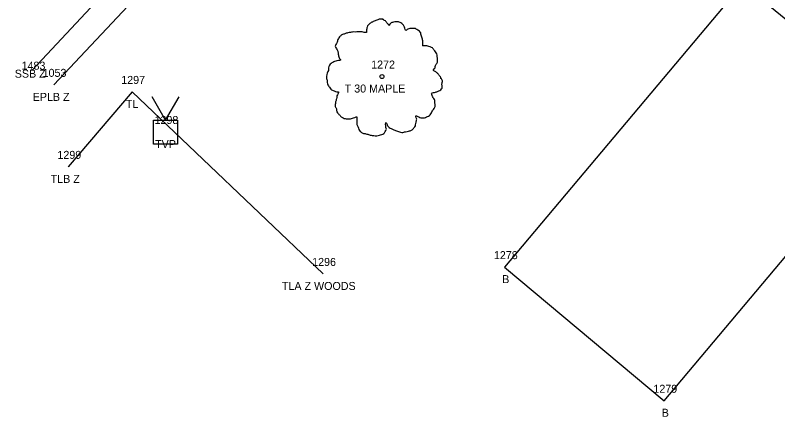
# Model space of a CAD drawing. Extents: x 1812340 to 1815011, y 1177659 to 1180159.
# Drawn here: x 1813841.8 to 1813937.1, y 1178154.3 to 1178204.5 of the extents above; entities that cross this region are included whole.
import ezdxf

# ---------------------------------------------------------------- set-up
doc = ezdxf.new("R2010")
doc.units = 0
for name, color, linetype in [('RD_EX_Bldg', 7, 'Continuous'), ('RD_EX_Bldg_txCode', 7, 'Continuous'), ('RD_EX_Road', 7, 'Continuous'), ('RD_EX_Road_txCode', 7, 'Continuous'), ('RD_EX_UT', 7, 'Continuous'), ('RD_EX_UT_txCode', 7, 'Continuous'), ('RD_EX_VEG', 7, 'Continuous'), ('RD_EX_VEG_txCode', 7, 'Continuous'), ('RD_SMD_Locator', 7, 'Continuous')]:
    doc.layers.add(name, color=color, linetype=linetype)

msp = doc.modelspace()

# ---------------------------------------------------------------- linework, layer by layer
at = {"layer": 'RD_EX_Bldg'}
msp.add_lwpolyline([(1813952.832, 1178191.893), (1813932.672, 1178208.432), (1813902.972, 1178172.996), (1813922.899, 1178156.295), (1813952.832, 1178191.893)], dxfattribs=at)
at = {"layer": 'RD_EX_Road'}
msp.add_lwpolyline([(1814062.161, 1178410.758), (1814056.57, 1178415.985), (1814052.145, 1178418.064), (1814044.495, 1178417.459), (1814039.532, 1178416.2), (1814027.176, 1178402.169), (1814022.797, 1178396.983), (1813991.686, 1178360.575), (1813959.638, 1178321.242), (1813927.093, 1178281.882), (1813899.481, 1178251.693), (1813888.904, 1178240.782), (1813846.632, 1178195.786)], dxfattribs=at)
at = {"layer": 'RD_EX_UT'}
for p, q in [((1813862.261, 1178217.196), (1813843.967, 1178197.681)), ((1813860.583, 1178191.39), (1813858.917, 1178194.276)), ((1813860.583, 1178191.39), (1813862.324, 1178194.276))]:
    msp.add_line(p, q, dxfattribs=at)
msp.add_lwpolyline([(1813859.083, 1178188.39), (1813859.083, 1178191.39), (1813862.083, 1178191.39), (1813862.083, 1178188.39)], close=True, dxfattribs=at)
at = {"layer": 'RD_EX_VEG'}
msp.add_lwpolyline([(1813880.294, 1178172.148), (1813856.418, 1178194.9), (1813848.446, 1178185.531)], dxfattribs=at)
for centre, radius in [((1813887.639, 1178196.824), 0.25), ((1813887.626, 1178196.805), 0.0001)]:
    msp.add_circle(centre, radius, dxfattribs=at)
for points in [[(1813887.771, 1178203.991), (1813887.471, 1178204.016), (1813887.146, 1178203.916), (1813886.896, 1178203.816), (1813886.671, 1178203.741), (1813886.446, 1178203.641), (1813886.146, 1178203.467), (1813885.921, 1178203.267), (1813885.796, 1178203.017), (1813885.746, 1178202.792), (1813885.696, 1178202.517), (1813885.696, 1178202.342), (1813885.572, 1178202.317), (1813885.422, 1178202.342), (1813885.172, 1178202.417), (1813884.922, 1178202.417), (1813884.672, 1178202.417), (1813884.322, 1178202.392), (1813883.972, 1178202.392), (1813883.697, 1178202.342), (1813883.372, 1178202.292), (1813882.998, 1178202.167), (1813882.648, 1178202.042), (1813882.348, 1178201.792), (1813882.098, 1178201.318), (1813881.973, 1178200.968), (1813881.823, 1178200.718), (1813881.973, 1178200.268), (1813882.148, 1178199.918), (1813882.173, 1178199.718), (1813882.248, 1178199.293), (1813882.348, 1178199.069), (1813882.473, 1178198.869), (1813882.398, 1178198.844), (1813882.023, 1178198.794), (1813881.723, 1178198.694), (1813881.298, 1178198.469), (1813881.073, 1178198.244), (1813880.973, 1178197.919), (1813880.949, 1178197.569), (1813880.849, 1178197.369), (1813880.774, 1178197.094), (1813880.749, 1178197.019), (1813880.699, 1178196.695), (1813880.799, 1178196.245), (1813880.824, 1178195.895), (1813880.949, 1178195.67), (1813881.098, 1178195.495), (1813881.273, 1178195.245), (1813881.673, 1178195.02), (1813881.998, 1178194.92), (1813882.198, 1178194.895), (1813882.023, 1178194.396), (1813881.973, 1178194.046), (1813881.848, 1178193.646), (1813881.848, 1178193.571), (1813881.798, 1178193.096), (1813881.948, 1178192.771), (1813882.023, 1178192.396), (1813882.198, 1178192.172), (1813882.473, 1178191.872), (1813882.798, 1178191.647), (1813883.298, 1178191.522), (1813883.697, 1178191.547), (1813884.272, 1178191.722), (1813884.522, 1178191.797), (1813884.497, 1178191.622), (1813884.522, 1178191.247), (1813884.522, 1178190.822), (1813884.672, 1178190.497), (1813884.772, 1178190.222), (1813884.922, 1178189.972), (1813885.247, 1178189.748), (1813885.646, 1178189.673), (1813886.071, 1178189.523), (1813886.521, 1178189.448), (1813887.021, 1178189.423), (1813887.621, 1178189.573), (1813887.895, 1178189.698), (1813887.995, 1178189.873), (1813888.195, 1178190.247), (1813888.145, 1178190.472), (1813888.17, 1178191.072), (1813888.27, 1178190.897), (1813888.445, 1178190.547), (1813888.945, 1178190.247), (1813889.345, 1178190.072), (1813889.82, 1178189.922), (1813890.12, 1178189.848), (1813890.594, 1178189.922), (1813890.969, 1178189.997), (1813891.344, 1178190.122), (1813891.644, 1178190.397), (1813891.819, 1178190.672), (1813891.869, 1178190.947), (1813891.944, 1178191.322), (1813891.994, 1178191.497)], [(1813891.994, 1178191.497), (1813891.919, 1178191.672), (1813891.869, 1178191.922), (1813891.944, 1178191.897), (1813892.119, 1178191.847), (1813892.394, 1178191.722), (1813892.618, 1178191.647), (1813892.943, 1178191.672), (1813893.218, 1178191.772), (1813893.668, 1178192.047), (1813893.943, 1178192.521), (1813894.218, 1178192.921), (1813894.293, 1178193.246), (1813894.243, 1178193.471), (1813894.218, 1178193.971), (1813894.018, 1178194.221), (1813893.968, 1178194.346), (1813893.868, 1178194.745), (1813893.943, 1178194.795), (1813894.218, 1178194.845), (1813894.593, 1178194.97), (1813894.867, 1178195.095), (1813895.092, 1178195.27), (1813895.167, 1178195.495), (1813895.142, 1178195.895), (1813895.192, 1178196.295), (1813895.117, 1178196.445), (1813895.017, 1178196.595), (1813894.942, 1178196.795), (1813894.792, 1178196.944), (1813894.693, 1178197.094), (1813894.593, 1178197.194), (1813894.468, 1178197.344), (1813894.293, 1178197.469), (1813894.143, 1178197.519), (1813894.093, 1178197.669), (1813894.243, 1178197.869), (1813894.293, 1178197.969), (1813894.318, 1178198.194), (1813894.543, 1178198.544), (1813894.593, 1178198.944), (1813894.543, 1178199.368), (1813894.493, 1178199.643), (1813894.343, 1178199.918), (1813894.143, 1178200.168), (1813894.018, 1178200.343), (1813893.843, 1178200.468), (1813893.518, 1178200.593), (1813893.268, 1178200.643), (1813892.918, 1178200.643), (1813892.718, 1178200.693), (1813892.743, 1178200.743), (1813892.743, 1178200.893), (1813892.743, 1178201.168), (1813892.668, 1178201.617), (1813892.518, 1178202.117), (1813892.518, 1178202.142), (1813892.418, 1178202.392), (1813892.194, 1178202.592), (1813892.019, 1178202.692), (1813891.819, 1178202.817), (1813891.569, 1178202.842), (1813891.269, 1178202.842), (1813890.994, 1178202.792), (1813890.794, 1178202.692), (1813890.619, 1178202.567), (1813890.544, 1178202.717), (1813890.444, 1178203.017), (1813890.394, 1178203.167), (1813890.244, 1178203.342), (1813890.02, 1178203.542), (1813889.57, 1178203.666), (1813888.945, 1178203.592), (1813888.645, 1178203.392), (1813888.495, 1178203.217), (1813888.445, 1178203.342), (1813888.245, 1178203.542), (1813888.145, 1178203.716), (1813887.97, 1178203.841), (1813887.821, 1178203.941), (1813887.721, 1178203.991)]]:
    msp.add_spline(points, degree=3, dxfattribs=at)
at = {"layer": 'RD_SMD_Locator'}
for centre in [(1813843.967, 1178197.681), (1813846.632, 1178195.786), (1813856.418, 1178194.9), (1813848.446, 1178185.531), (1813902.972, 1178172.996), (1813880.294, 1178172.148), (1813922.899, 1178156.295)]:
    msp.add_circle(centre, 0.001, dxfattribs=at)

# ---------------------------------------------------------------- texts
at = {"layer": 'RD_EX_Bldg_txCode'}
for s, p in [('1278', (1813901.626, 1178173.996)), ('B', (1813902.665, 1178170.996)), ('1279', (1813921.553, 1178157.295)), ('B', (1813922.592, 1178154.295))]:
    msp.add_text(s, height=1, dxfattribs=at).set_placement(p)
at = {"layer": 'RD_EX_Road_txCode'}
for s, p in [('1053', (1813845.246, 1178196.786)), ('EPLB Z', (1813844.01, 1178193.786))]:
    msp.add_text(s, height=1, dxfattribs=at).set_placement(p)
at = {"layer": 'RD_EX_UT_txCode'}
for s, p in [('1483', (1813842.62, 1178197.681)), ('SSB Z', (1813841.77, 1178196.681)), ('1298', (1813859.237, 1178190.89)), ('TVP', (1813859.3, 1178187.89))]:
    msp.add_text(s, height=1, dxfattribs=at).set_placement(p)
at = {"layer": 'RD_EX_VEG_txCode'}
for s, p in [('1272', (1813886.292, 1178197.824)), ('1297', (1813855.071, 1178195.9)), ('T 30 MAPLE', (1813882.989, 1178194.824)), ('TL', (1813855.646, 1178192.9)), ('1299', (1813847.099, 1178186.531)), ('TLB Z', (1813846.257, 1178183.531)), ('1296', (1813878.924, 1178173.148)), ('TLA Z WOODS', (1813875.145, 1178170.148))]:
    msp.add_text(s, height=1, dxfattribs=at).set_placement(p)

doc.saveas('drawing.dxf')
